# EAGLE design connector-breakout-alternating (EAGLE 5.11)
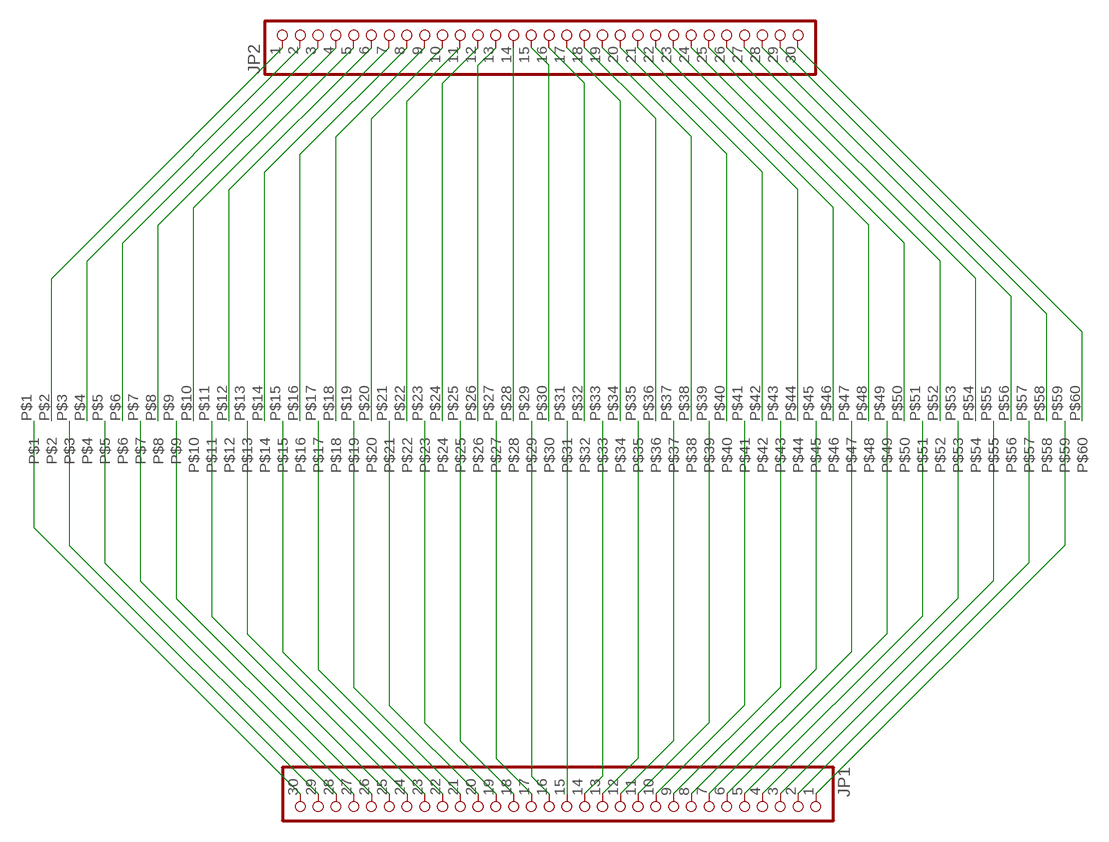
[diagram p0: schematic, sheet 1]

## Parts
JP1  PINHD-1X30  [1X30]
JP2  PINHD-1X30  [1X30]
U$1  FPC-60-CHUMBYALT  [FPC-60-ALT-CHUMBY]

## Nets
N$1: JP1.30 U$1.P$1
N$2: JP1.29 U$1.P$3
N$3: JP1.28 U$1.P$5
N$4: JP1.27 U$1.P$7
N$5: JP1.26 U$1.P$9
N$6: JP1.25 U$1.P$11
N$7: JP1.24 U$1.P$13
N$8: JP1.23 U$1.P$15
N$9: JP1.22 U$1.P$17
N$10: JP1.21 U$1.P$19
N$11: JP1.20 U$1.P$21
N$12: JP1.19 U$1.P$23
N$13: JP1.18 U$1.P$25
N$14: JP1.17 U$1.P$27
N$15: JP1.16 U$1.P$29
N$16: JP1.15 U$1.P$31
N$17: JP1.14 U$1.P$33
N$18: JP1.13 U$1.P$35
N$19: JP1.12 U$1.P$37
N$20: JP1.11 U$1.P$39
N$21: JP1.10 U$1.P$41
N$22: JP1.9 U$1.P$43
N$23: JP1.8 U$1.P$45
N$24: JP1.7 U$1.P$47
N$25: JP1.6 U$1.P$49
N$26: JP1.5 U$1.P$51
N$27: JP1.4 U$1.P$53
N$28: JP1.3 U$1.P$55
N$29: JP1.2 U$1.P$57
N$30: JP1.1 U$1.P$59
N$31: JP2.1 U$1.P$2
N$32: JP2.2 U$1.P$4
N$33: JP2.3 U$1.P$6
N$34: JP2.4 U$1.P$8
N$35: JP2.5 U$1.P$10
N$36: JP2.6 U$1.P$12
N$37: JP2.7 U$1.P$14
N$38: JP2.8 U$1.P$16
N$39: JP2.9 U$1.P$18
N$40: JP2.10 U$1.P$20
N$41: JP2.11 U$1.P$22
N$42: JP2.12 U$1.P$24
N$43: JP2.13 U$1.P$26
N$44: JP2.14 U$1.P$28
N$45: JP2.15 U$1.P$30
N$46: JP2.16 U$1.P$32
N$47: JP2.17 U$1.P$34
N$48: JP2.18 U$1.P$36
N$49: JP2.19 U$1.P$38
N$50: JP2.20 U$1.P$40
N$51: JP2.21 U$1.P$42
N$52: JP2.22 U$1.P$44
N$53: JP2.23 U$1.P$46
N$54: JP2.24 U$1.P$48
N$55: JP2.25 U$1.P$50
N$56: JP2.26 U$1.P$52
N$57: JP2.27 U$1.P$54
N$58: JP2.28 U$1.P$56
N$59: JP2.29 U$1.P$58
N$60: JP2.30 U$1.P$60

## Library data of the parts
JP1 JP2 = pinhead:PINHD-1X30: PIN HEADER
U$1 = trl:FPC-60-CHUMBY

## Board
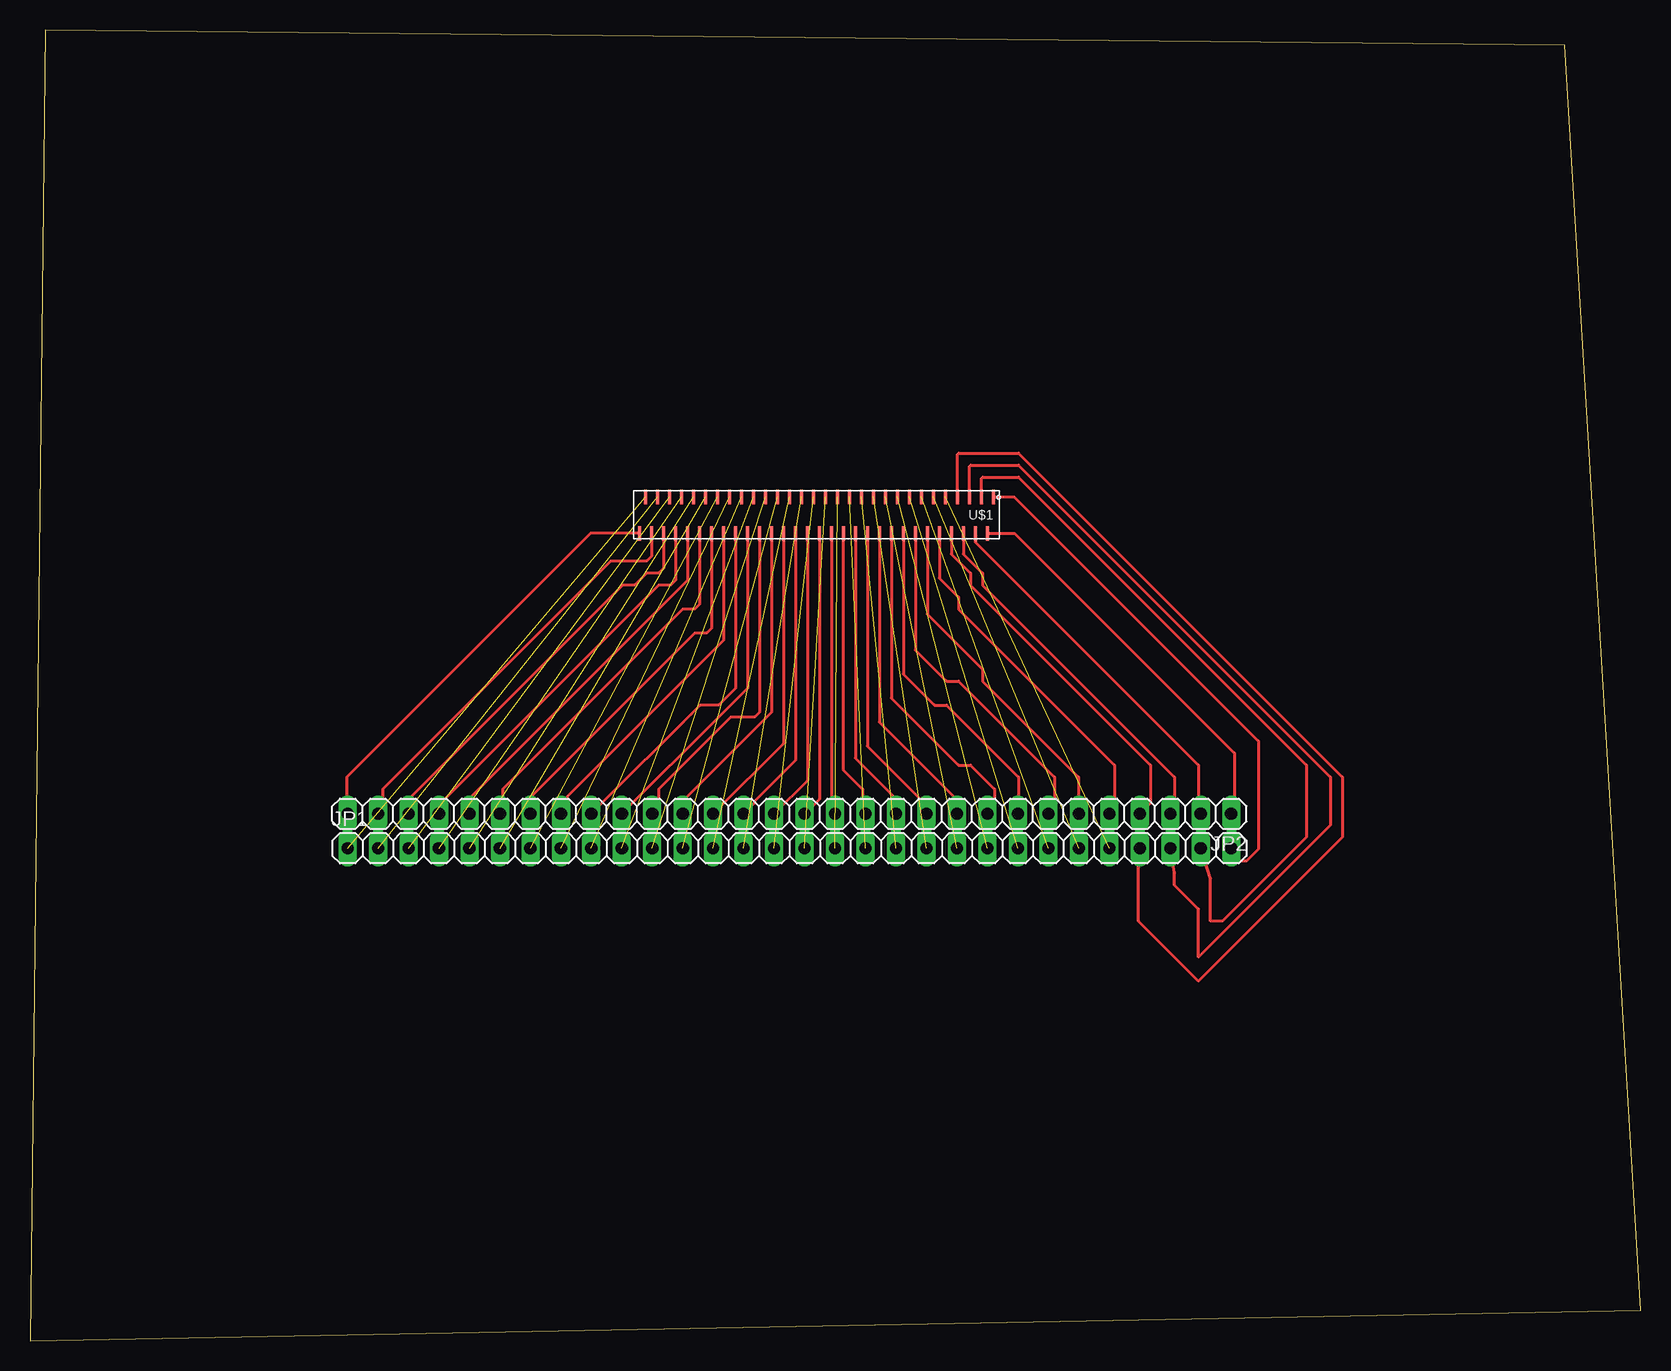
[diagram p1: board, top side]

Size 134.29 x 109.21 mm. Coordinates in mm from the lower left corner, seen from the top.
Outline: 0,0 134.29,2.54 127.94,107.94 1.27,109.21 0,0
Copper layers (1*16): Top 0.035mm / dielectric 1.5mm / Bottom 0.035mm
Design rules "default": minimum track width 10mil, minimum drill 24mil, track to track 8mil, track to pad 8mil, pad to pad 8mil, via to via 8mil, smd to smd 8mil, copper to edge 40mil, drill to drill 8mil, minimum pad ring 10mil, minimum via ring 8mil, stop-mask expansion 4mil, vias tented up to drill 0mil, thermal gap 10mil

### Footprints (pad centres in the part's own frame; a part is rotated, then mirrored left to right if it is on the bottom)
1X30 = drill 1.016 long: 1 -36.83,0; 2 -34.29,0; 3 -31.75,0; 4 -29.21,0; 5 -26.67,0; 6 -24.13,0; 7 -21.59,0; 8 -19.05,0; 9 -16.51,0; 10 -13.97,0; 11 -11.43,0; 12 -8.89,0; 13 -6.35,0; 14 -3.81,0; 15 -1.27,0; 16 1.27,0; 17 3.81,0; 18 6.35,0; 19 8.89,0; 20 11.43,0; 21 13.97,0; 22 16.51,0; 23 19.05,0; 24 21.59,0; 25 24.13,0; 26 26.67,0; 27 29.21,0; 28 31.75,0; 29 34.29,0; 30 36.83,0
FPC-60-ALT-CHUMBY = smd 0.25 x 1.2: P$1 -14,-1.5; P$2 -13.5,1.55; P$3 -13,-1.5; P$4 -12.5,1.55; P$5 -12,-1.5; P$6 -11.5,1.55; P$7 -11,-1.5; P$8 -10.5,1.55; P$9 -10,-1.5; P$10 -9.5,1.55; P$11 -9,-1.5; P$12 -8.5,1.55; P$13 -8,-1.5; P$14 -7.5,1.55; P$15 -7,-1.5; P$16 -6.5,1.55; P$17 -6,-1.5; P$18 -5.5,1.55; P$19 -5,-1.5; P$20 -4.5,1.55; P$21 -4,-1.5; P$22 -3.5,1.55; P$23 -3,-1.5; P$24 -2.5,1.55; P$25 -2,-1.5; P$26 -1.5,1.55; P$27 -1,-1.5; P$28 -0.5,1.55; P$29 0,-1.5; P$30 0.5,1.55; P$31 1,-1.5; P$32 1.5,1.55; P$33 2,-1.5; P$34 2.5,1.55; P$35 3,-1.5; P$36 3.5,1.55; P$37 4,-1.5; P$38 4.5,1.55; P$39 5,-1.5; P$40 5.5,1.55; P$41 6,-1.5; P$42 6.5,1.55; P$43 7,-1.5; P$44 7.5,1.55; P$45 8,-1.5; P$46 8.5,1.55; P$47 9,-1.5; P$48 9.5,1.55; P$49 10,-1.5; P$50 10.5,1.55; P$51 11,-1.5; P$52 11.5,1.55; P$53 12,-1.5; P$54 12.5,1.55; P$55 13,-1.5; P$56 13.5,1.55; P$57 14,-1.5; P$58 14.5,1.55; P$59 15,-1.5; P$60 15.5,1.55

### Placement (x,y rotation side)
JP1  63.3,41.03 0 top
JP2  63.3,43.89 180 top
U$1  66.3,68.81 180 top

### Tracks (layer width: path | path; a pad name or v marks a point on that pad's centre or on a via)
N$1
  Top 0.254: U$1.P$1 82.03,70.31 102.4,49.94 102.4,40.94 101.4,39.94 100.74,39.94 JP1.30
N$2
  Top 0.254: U$1.P$3 79.3,71.84 79.4,71.94 82.4,71.94 106.4,47.94 106.4,41.94 99.4,34.94 98.4,34.94 98.4,38.52 JP1.29
N$3
  Top 0.254: U$1.P$5 78.3,72.84 78.4,72.94 82.4,72.94 108.4,46.94 108.4,42.94 97.4,31.94 97.4,35.94 95.4,37.94 95.4,38.98 JP1.28
N$4
  Top 0.254: U$1.P$7 77.3,73.84 77.4,73.94 82.4,73.94 109.4,46.94 109.4,41.94 97.4,29.94 92.4,34.94 92.4,39.44 | 92.4,39.94 92.4,39.44 | 92.4,39.44 JP1.27
N$5  (1 unrouted)
N$6  (1 unrouted)
N$7  (1 unrouted)
N$8  (1 unrouted)
N$9  (1 unrouted)
N$10  (1 unrouted)
N$11  (1 unrouted)
N$12  (1 unrouted)
N$13  (1 unrouted)
N$14  (1 unrouted)
N$15  (1 unrouted)
N$16  (1 unrouted)
N$17  (1 unrouted)
N$18  (1 unrouted)
N$19  (1 unrouted)
N$20  (1 unrouted)
N$21  (1 unrouted)
N$22  (1 unrouted)
N$23  (1 unrouted)
N$24  (1 unrouted)
N$25  (1 unrouted)
N$26  (1 unrouted)
N$27  (1 unrouted)
N$28  (1 unrouted)
N$29  (1 unrouted)
N$30  (1 unrouted)
N$31
  Top 0.254: U$1.P$2 82.08,67.26 100.4,48.94 100.4,44.16 JP2.1
N$32
  Top 0.254: U$1.P$4 78.8,66.54 97.4,47.94 97.4,44.08 JP2.2
N$33
  Top 0.254: U$1.P$6 77.8,65.54 79.4,63.94 79.4,62.94 95.4,46.94 95.4,44.24 JP2.3
N$34
  Top 0.254: U$1.P$8 76.8,65.54 78.4,63.94 78.4,62.94 93.4,47.94 93.4,44.78 JP2.4
N$35
  Top 0.254: U$1.P$10 75.8,63.54 77.4,61.94 77.4,60.94 90.4,47.94 90.4,44.32 JP2.5
N$36
  Top 0.254: U$1.P$12 74.8,60.54 79.4,55.94 79.4,54.94 87.4,46.94 87.4,43.86 | 87.4,42.94 87.4,43.86 | 87.4,43.86 JP2.6
N$37
  Top 0.254: U$1.P$14 73.8,57.54 76.4,54.94 77.4,54.94 85.4,46.94 85.4,44.4 JP2.7
N$38
  Top 0.254: U$1.P$16 72.8,55.54 75.4,52.94 76.4,52.94 82.4,46.94 82.4,43.94 JP2.8
N$39
  Top 0.254: U$1.P$18 71.8,53.54 77.4,47.94 78.4,47.94 80.4,45.94 80.4,44.48 JP2.9
N$40
  Top 0.254: U$1.P$20 70.8,51.54 77.4,44.94 77.4,44.02 JP2.10
N$41
  Top 0.254: U$1.P$22 69.8,49.54 74.4,44.94 74.4,44.22 JP2.11
N$42
  Top 0.254: U$1.P$24 68.8,48.54 72.4,44.94 72.4,44.1 JP2.12
N$43
  Top 0.254: U$1.P$26 67.8,47.54 69.4,45.94 69.4,44.14 JP2.13
N$44
  Top 0.254: U$1.P$28 66.8,44.2 JP2.14
N$45
  Top 0.254: U$1.P$30 65.8,45.12 JP2.15
N$46
  Top 0.254: U$1.P$32 64.8,46.66 JP2.16
N$47
  Top 0.254: U$1.P$34 63.8,48.34 60.4,44.94 60.4,44.8 JP2.17
N$48
  Top 0.254: U$1.P$36 62.8,49.74 JP2.18
N$49
  Top 0.254: U$1.P$38 61.8,52.34 54.4,44.94 JP2.19
N$50
  Top 0.254: U$1.P$40 60.8,52.34 60.4,51.94 58.4,51.94 52.4,45.94 52.4,44.42 JP2.20
N$51
  Top 0.254: U$1.P$42 59.8,54.34 57.4,51.94 57.38,51.94 JP2.21
N$52
  Top 0.254: U$1.P$44 58.8,54.34 57.4,52.94 55.84,52.94 JP2.22
N$53
  Top 0.254: U$1.P$46 57.8,58.34 44.4,44.94 44.4,44.04 JP2.23
N$54
  Top 0.254: U$1.P$48 56.8,59.34 56.4,58.94 55.4,58.94 41.4,44.94 41.4,44.2 JP2.24
N$55
  Top 0.254: U$1.P$50 55.8,61.34 55.4,60.94 54.4,60.94 39.4,45.94 39.4,44.12 JP2.25
N$56
  Top 0.254: U$1.P$52 54.8,63.34 36.4,44.94 36.4,44.12 JP2.26
N$57
  Top 0.254: U$1.P$54 53.8,63.34 53.4,62.94 52.4,62.94 34.4,44.94 34.4,44.2 JP2.27
N$58
  Top 0.254: U$1.P$56 52.8,64.34 52.4,63.94 51.4,63.94 50.4,62.94 49.4,62.94 31.4,44.94 31.4,44.04 JP2.28
N$59
  Top 0.254: U$1.P$58 51.8,65.34 51.4,64.94 48.4,64.94 29.4,45.94 29.4,44.28 JP2.29
N$60
  Top 0.254: U$1.P$60 46.72,67.26 26.4,46.94 26.4,43.96 JP2.30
